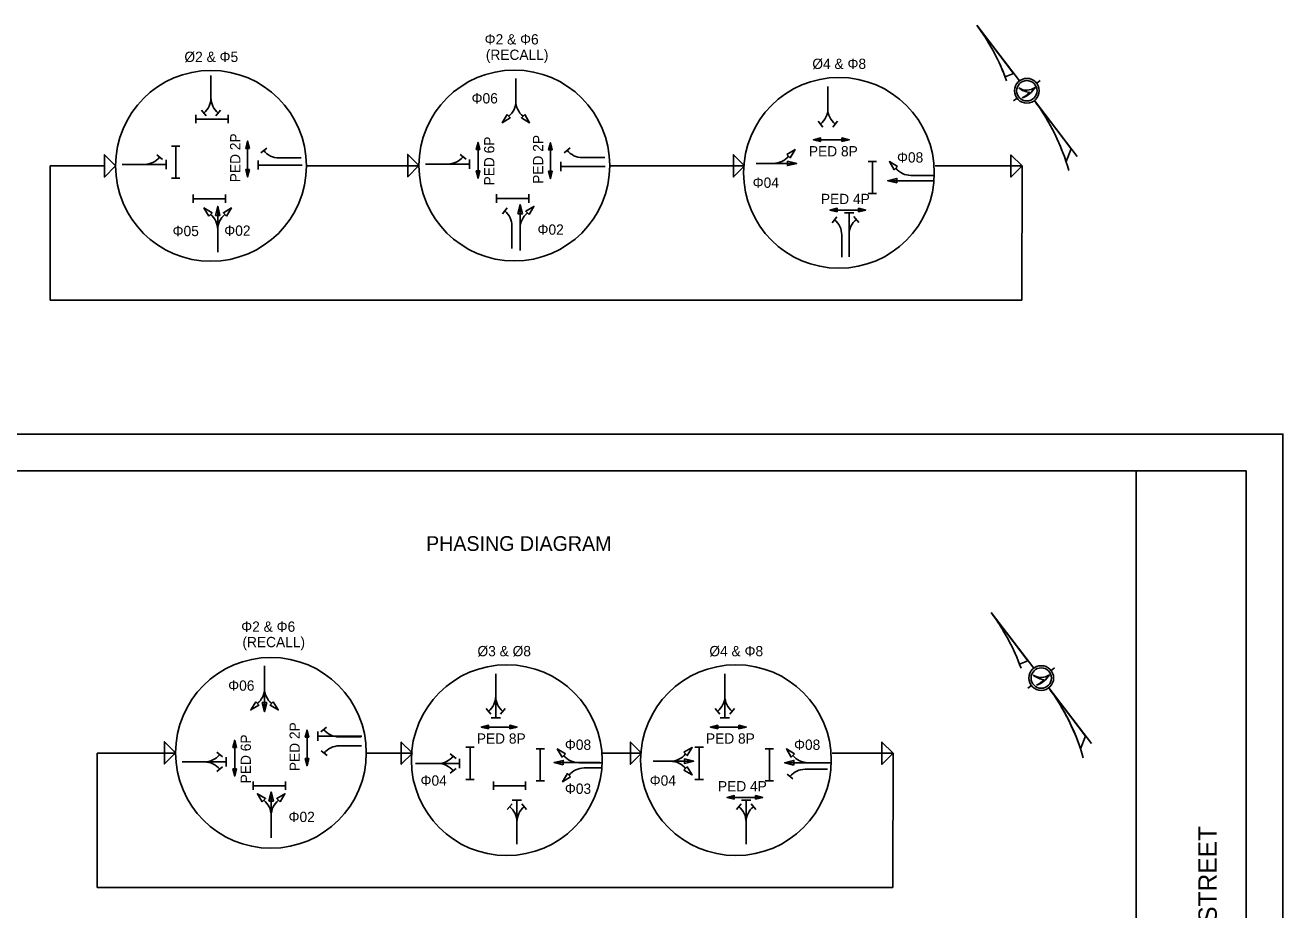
# Model space of a CAD drawing. Extents: x 0 to 680, y 0 to 551.
# Drawn here: x 337.3 to 680, y 310.4 to 551.4 of the extents above; entities that cross this region are included whole.
import ezdxf

# ---------------------------------------------------------------- set-up
doc = ezdxf.new("R2010")
doc.units = 0
for name, color, linetype in [('SG_P_Text', 7, 'Continuous'), ('SH_Border', 7, 'Continuous'), ('SH_Cut_Line', 7, 'Continuous'), ('SH_Data', 7, 'Continuous'), ('SH_Text', 7, 'Continuous')]:
    doc.layers.add(name, color=color, linetype=linetype)

msp = doc.modelspace()

# ---------------------------------------------------------------- linework, layer by layer
at = {"layer": 'SG_P_Text'}
for p, q in [((387.94, 537.7), (387.94, 531.59)), ((387.94, 537.7), (387.94, 531.59)), ((471, 536.85), (471, 530.74)), ((471.04, 536.85), (471.04, 530.74)), ((556.02, 534.7), (556.02, 528.59)), ((556.02, 534.7), (556.02, 528.59)), ((386.6, 526.66), (385.32, 528.25)), ((389.28, 526.66), (390.56, 528.25)), ((383.82, 526.97), (383.82, 524.69)), ((383.82, 525.83), (392.59, 525.83)), ((392.59, 526.97), (392.59, 524.69)), ((554.68, 523.66), (553.4, 525.25)), ((557.35, 523.66), (558.64, 525.25)), ((379.49, 518.46), (377.2, 518.46)), ((378.35, 509.68), (378.35, 518.46)), ((397.91, 510.06), (397.91, 519.82)), ((401.53, 516.58), (403.12, 517.86)), ((460.74, 509.71), (460.74, 519.47)), ((480.43, 509.63), (480.43, 519.38)), ((484.19, 516.67), (485.78, 517.95)), ((552.08, 520.19), (561.84, 520.19)), ((374.76, 514.83), (373.17, 516.11)), ((375.74, 514.76), (375.74, 512.22)), ((400.79, 512.04), (400.79, 514.57)), ((412.56, 515.24), (406.45, 515.24)), ((457.43, 514.91), (455.83, 516.19)), ((458.4, 514.84), (458.4, 512.31)), ((483.31, 511.6), (483.31, 514.14)), ((495.23, 515.33), (489.12, 515.33)), ((569.3, 514.3), (567.01, 514.3)), ((568.16, 505.52), (568.16, 514.3)), ((344.11, 476.49), (344.17, 513.07)), ((344.17, 513.07), (358.92, 513.07)), ((363.72, 513.49), (375.74, 513.49)), ((363.72, 513.49), (369.83, 513.49)), ((412.8, 513.3), (400.79, 513.3)), ((444.61, 513.08), (413.93, 513.07)), ((446.39, 513.57), (458.4, 513.57)), ((446.39, 513.57), (452.5, 513.57)), ((495.32, 512.87), (483.31, 512.87)), ((533.31, 513.08), (496.59, 513.08)), ((536.52, 513.76), (541.19, 513.76)), ((547.54, 513.76), (536.52, 513.76)), ((608.94, 513.05), (585.29, 513.08)), ((608.88, 476.49), (608.94, 513.05)), ((379.49, 509.68), (377.2, 509.68)), ((572.33, 509.04), (584.79, 509.04)), ((584.79, 510.47), (578.68, 510.47)), ((383.11, 505.24), (383.11, 502.96)), ((391.89, 504.1), (383.11, 504.1)), ((391.89, 505.24), (391.89, 502.96)), ((465.78, 505.33), (465.78, 503.04)), ((474.55, 504.19), (465.78, 504.19)), ((474.55, 505.33), (474.55, 503.04)), ((569.3, 505.52), (567.01, 505.52)), ((389.78, 502.06), (389.78, 489.6)), ((468.63, 501.6), (467.34, 500)), ((472.18, 502.47), (472.18, 490.01)), ((556.6, 501.03), (566.35, 501.03)), ((558.48, 499.19), (557.2, 497.6)), ((560.54, 500.26), (563.08, 500.26)), ((561.81, 488.25), (561.81, 500.26)), ((563.15, 499.29), (564.43, 497.69)), ((389.78, 489.6), (389.78, 495.71)), ((389.78, 489.6), (389.78, 495.71)), ((469.96, 490.56), (469.96, 496.67)), ((472.18, 490.01), (472.18, 496.12)), ((559.82, 488.16), (559.82, 494.27)), ((561.81, 488.25), (561.81, 494.36)), ((608.88, 476.49), (344.11, 476.49)), ((402.51, 376.85), (402.51, 370.74)), ((402.55, 376.85), (402.55, 370.74)), ((402.55, 364.39), (402.55, 376.85)), ((465.52, 374.7), (465.52, 368.59)), ((465.52, 374.7), (465.52, 368.59)), ((465.52, 374.7), (465.52, 362.69)), ((527.96, 374.7), (527.96, 368.59)), ((527.96, 374.7), (527.96, 368.59)), ((527.96, 374.7), (527.96, 362.69)), ((464.18, 363.66), (462.9, 365.25)), ((466.86, 363.66), (468.14, 365.25)), ((526.62, 363.66), (525.34, 365.25)), ((529.3, 363.66), (530.58, 365.25)), ((417.87, 358.87), (419.46, 360.15)), ((461.59, 360.19), (471.34, 360.19)), ((466.79, 362.69), (464.25, 362.69)), ((524.03, 360.19), (533.78, 360.19)), ((529.23, 362.69), (526.69, 362.69)), ((394.42, 346.84), (394.42, 356.59)), ((414.11, 349.63), (414.11, 359.38)), ((417.04, 356.41), (417.04, 358.95)), ((429.05, 357.68), (417.04, 357.68)), ((428.91, 357.52), (422.8, 357.53)), ((356.9, 316.49), (356.96, 353.08)), ((378.29, 353.08), (356.96, 353.08)), ((391.11, 352.04), (389.51, 353.32)), ((417.96, 353.73), (419.56, 352.45)), ((429, 355.07), (422.89, 355.07)), ((442.62, 353.08), (430.27, 353.08)), ((459.66, 354.72), (457.38, 354.72)), ((458.52, 345.94), (458.52, 354.72)), ((478.8, 354.3), (476.52, 354.3)), ((477.66, 345.52), (477.66, 354.3)), ((505.25, 353.08), (494.46, 353.08)), ((522.1, 354.72), (519.82, 354.72)), ((520.96, 345.94), (520.96, 354.72)), ((541.24, 354.3), (538.96, 354.3)), ((540.1, 345.52), (540.1, 354.3)), ((573.8, 353.05), (557.24, 353.08)), ((573.74, 316.49), (573.8, 353.05)), ((380.07, 350.7), (392.08, 350.7)), ((380.07, 350.7), (386.18, 350.7)), ((380.07, 350.7), (386.18, 350.7)), ((392.08, 351.96), (392.08, 349.43)), ((443.69, 350.26), (455.7, 350.26)), ((443.69, 350.26), (449.8, 350.26)), ((443.69, 350.26), (449.8, 350.26)), ((454.73, 351.6), (453.13, 352.88)), ((455.7, 351.53), (455.7, 349)), ((481.44, 350.5), (493.9, 350.5)), ((494.3, 350.47), (488.19, 350.48)), ((508.47, 350.88), (513.13, 350.88)), ((519.48, 350.88), (508.47, 350.88)), ((508.47, 350.88), (513.13, 350.88)), ((544.28, 350.47), (556.74, 350.47)), ((556.74, 350.47), (550.63, 350.48)), ((391.11, 349.36), (389.51, 348.08)), ((454.73, 348.92), (453.13, 347.64)), ((494.3, 349.04), (489.63, 349.04)), ((544.9, 347.36), (546.5, 346.08)), ((555.94, 348.7), (549.83, 348.7)), ((399.46, 345.33), (399.46, 343.05)), ((408.23, 344.19), (399.46, 344.19)), ((408.23, 345.33), (408.23, 343.05)), ((459.66, 345.94), (457.38, 345.94)), ((464.9, 345.33), (464.9, 343.05)), ((473.67, 344.19), (464.9, 344.19)), ((473.67, 345.33), (473.67, 343.05)), ((478.8, 345.52), (476.52, 345.52)), ((522.1, 345.94), (519.82, 345.94)), ((541.24, 345.52), (538.96, 345.52)), ((404.34, 342.47), (404.34, 330.01)), ((469.97, 339.29), (468.69, 337.69)), ((470.04, 340.26), (472.58, 340.26)), ((471.31, 328.25), (471.31, 340.26)), ((472.65, 339.29), (473.93, 337.69)), ((528.55, 341.03), (538.3, 341.03)), ((532.41, 339.29), (531.13, 337.69)), ((532.48, 340.26), (535.02, 340.26)), ((533.75, 328.25), (533.75, 340.26)), ((535.09, 339.29), (536.37, 337.69)), ((404.34, 330.01), (404.34, 336.12)), ((404.34, 330.01), (404.34, 336.12)), ((471.31, 328.25), (471.31, 334.36)), ((471.31, 328.25), (471.31, 334.36)), ((533.75, 328.25), (533.75, 334.36)), ((533.75, 328.25), (533.75, 334.36)), ((573.74, 316.49), (356.9, 316.49))]:
    msp.add_line(p, q, dxfattribs=at)
for points in [[(468.62, 527.05), (467.29, 524.83), (469.5, 526.16)], [(473.42, 527.05), (474.75, 524.83), (472.54, 526.16)], [(398.41, 517.84), (397.91, 519.82), (397.42, 517.84)], [(461.23, 517.49), (460.74, 519.47), (460.24, 517.49)], [(480.93, 517.4), (480.43, 519.38), (479.94, 517.4)], [(544.88, 516.18), (547.09, 517.51), (545.76, 515.3)], [(554.06, 519.7), (552.08, 520.19), (554.06, 520.69)], [(559.86, 519.7), (561.84, 520.19), (559.86, 520.69)], [(361.95, 513.07), (358.92, 516.11), (358.91, 510.04)], [(444.61, 513.16), (441.58, 516.19), (441.58, 510.13)], [(533.31, 513.08), (530.28, 516.11), (530.28, 510.05)], [(545.04, 514.39), (547.54, 513.76), (545.04, 513.14)], [(574.99, 512.9), (572.78, 514.22), (574.11, 512.01)], [(608.94, 513.05), (605.91, 516.08), (605.91, 510.02)], [(398.41, 512.04), (397.91, 510.06), (397.42, 512.04)], [(461.23, 511.69), (460.74, 509.71), (460.24, 511.69)], [(480.93, 511.61), (480.43, 509.63), (479.94, 511.61)], [(574.83, 508.41), (572.33, 509.04), (574.83, 509.66)], [(387.36, 499.4), (386.03, 501.62), (388.24, 500.29)], [(389.15, 499.56), (389.78, 502.06), (390.4, 499.56)], [(392.2, 499.4), (393.53, 501.61), (391.32, 500.29)], [(471.55, 499.97), (472.18, 502.47), (472.8, 499.97)], [(474.6, 499.81), (475.92, 502.02), (473.72, 500.69)], [(558.58, 500.54), (556.6, 501.03), (558.58, 501.53)], [(564.38, 500.54), (566.35, 501.03), (564.38, 501.53)], [(400.13, 367.05), (398.8, 364.84), (401.01, 366.17)], [(403.17, 366.89), (402.55, 364.39), (401.92, 366.89)], [(404.93, 367.05), (406.26, 364.84), (404.05, 366.17)], [(463.57, 359.7), (461.59, 360.19), (463.57, 360.69)], [(469.36, 359.7), (471.34, 360.19), (469.36, 360.69)], [(526.01, 359.7), (524.03, 360.19), (526.01, 360.69)], [(531.8, 359.7), (533.78, 360.19), (531.8, 360.69)], [(394.91, 354.61), (394.42, 356.59), (393.92, 354.61)], [(414.61, 357.41), (414.11, 359.38), (413.62, 357.41)], [(378.29, 353.16), (375.26, 356.19), (375.26, 350.13)], [(442.81, 353.08), (439.78, 356.11), (439.78, 350.05)], [(484.5, 352.9), (482.28, 354.22), (483.61, 352.01)], [(505.25, 353.08), (502.22, 356.11), (502.22, 350.05)], [(516.82, 353.31), (519.04, 354.63), (517.71, 352.42)], [(546.94, 352.9), (544.73, 354.22), (546.05, 352.01)], [(573.8, 353.05), (570.77, 356.09), (570.77, 350.02)], [(414.61, 351.61), (414.11, 349.63), (413.62, 351.61)], [(483.94, 349.87), (481.44, 350.5), (483.94, 351.12)], [(516.98, 351.51), (519.48, 350.88), (516.98, 350.26)], [(546.78, 349.85), (544.28, 350.47), (546.78, 351.1)], [(394.91, 348.82), (394.42, 346.84), (393.92, 348.82)], [(485.94, 346.62), (483.73, 345.29), (485.06, 347.5)], [(516.82, 348.46), (519.04, 347.14), (517.71, 349.35)], [(401.92, 339.81), (400.6, 342.02), (402.8, 340.69)], [(403.72, 339.97), (404.34, 342.47), (404.97, 339.97)], [(406.77, 339.81), (408.09, 342.02), (405.88, 340.69)], [(530.52, 340.54), (528.55, 341.03), (530.52, 341.53)], [(536.32, 340.54), (538.3, 341.03), (536.32, 341.53)]]:
    msp.add_lwpolyline(points, close=True, dxfattribs=at)
for centre in [(387.94, 513.07), (470.6, 513.16), (559.04, 511.17), (404.28, 353.16), (468.54, 351.17), (530.98, 351.17)]:
    msp.add_circle(centre, 25.99, dxfattribs=at)
for centre, start, end in [((382.64, 531.59), 308.7993, 0), ((393.24, 531.59), 180, 231.2007), ((465.74, 530.74), 308.7993, 0), ((476.3, 530.74), 180, 231.2007), ((550.72, 528.59), 308.7993, 0), ((561.32, 528.59), 180, 231.2007), ((369.83, 518.79), 270, 321.2007), ((406.46, 520.54), 218.7864, 269.9871), ((452.5, 518.87), 270, 321.2007), ((489.12, 520.63), 218.7864, 269.9871), ((541.19, 519.06), 270, 321.2007), ((578.68, 515.77), 218.7864, 269.9871), ((464.66, 496.67), 360, 51.2007), ((384.48, 495.71), 360, 51.2007), ((395.08, 495.71), 128.7864, 179.9871), ((477.48, 496.12), 128.7864, 179.9871), ((554.52, 494.27), 360, 51.2007), ((567.11, 494.36), 128.7993, 180), ((397.25, 370.74), 308.7993, 0), ((407.81, 370.74), 180, 231.2007), ((460.22, 368.59), 308.7993, 0), ((470.82, 368.59), 180, 231.2007), ((522.66, 368.59), 308.7993, 0), ((533.26, 368.59), 180, 231.2007), ((422.8, 362.83), 218.7864, 269.9871), ((422.89, 349.77), 90.0129, 141.2136), ((386.18, 356), 270, 321.2007), ((386.18, 345.4), 38.7993, 90), ((449.8, 355.56), 270, 321.2007), ((449.8, 344.96), 38.7993, 90), ((488.19, 355.78), 218.7864, 269.9871), ((513.13, 356.18), 270, 321.2007), ((513.13, 345.58), 38.7993, 90), ((550.63, 355.78), 218.7864, 269.9871), ((489.63, 343.74), 90, 141.2007), ((549.83, 343.4), 90.0129, 141.2136), ((399.04, 336.12), 0.0129, 51.2136), ((409.65, 336.12), 128.7864, 179.9871), ((466.01, 334.36), 360, 51.2007), ((476.61, 334.36), 128.7993, 180), ((528.45, 334.36), 360, 51.2007), ((539.05, 334.36), 128.7993, 180)]:
    msp.add_arc(centre, 5.3, start, end, dxfattribs=at)
at = {"layer": 'SH_Border'}
msp.add_line((640, 10), (640, 430), dxfattribs=at)
msp.add_lwpolyline([(30, 430), (670, 430), (670, 10), (30, 10)], close=True, dxfattribs=at)
at = {"layer": 'SH_Cut_Line'}
msp.add_lwpolyline([(0, 0), (680, 0), (680, 440), (0, 440)], close=True, dxfattribs=at)
at = {"layer": 'SH_Data'}
for p, q in [((608.2, 536.22), (596.58, 551.41)), ((604.34, 537.33), (606.64, 538.26)), ((612.93, 535.59), (613.89, 536.32)), ((606.62, 530.76), (607.57, 531.49)), ((623.92, 515.67), (612.3, 530.86)), ((622.33, 517.75), (620.95, 514.26)), ((612.12, 376.22), (600.5, 391.41)), ((608.26, 377.33), (610.56, 378.27)), ((616.86, 375.59), (617.81, 376.32)), ((610.54, 370.76), (611.49, 371.49)), ((627.85, 355.67), (616.23, 370.86)), ((626.25, 357.75), (624.87, 354.27))]:
    msp.add_line(p, q, dxfattribs=at)
for points in [[(604.33, 537.32), (604.34, 537.33), (606.64, 538.26), (596.58, 551.41)], [(620.95, 514.26), (622.33, 517.75), (612.3, 530.86)], [(608.25, 377.33), (608.26, 377.33), (610.56, 378.27), (600.5, 391.41)], [(624.87, 354.27), (626.25, 357.75), (616.23, 370.86)]]:
    msp.add_lwpolyline(points, dxfattribs=at)
for centre, radius in [((610.25, 533.54), 3.37), ((610.25, 533.54), 2.78), ((614.17, 373.54), 3.37), ((614.17, 373.54), 2.78)]:
    msp.add_circle(centre, radius, dxfattribs=at)
for centre, radius, start, end in [((549.11, 516.14), 59.14, 19.8318, 36.6112), ((549.11, 516.14), 59.14, 20.9919, 36.6112), ((610.19, 537.51), 3.82, 236.574, 306.7874), ((611.52, 538.45), 5.38, 230.2721, 264.7306), ((606.67, 537.95), 6.79, 289.9039, 328.9025), ((604.93, 539.13), 8.57, 298.1442, 315.2899), ((564.83, 495.59), 59.14, 15.9219, 36.6112), ((564.83, 495.59), 59.14, 18.4101, 36.6112), ((553.03, 356.14), 59.14, 19.8318, 36.6112), ((553.03, 356.14), 59.14, 20.9919, 36.6112), ((614.11, 377.51), 3.82, 236.574, 306.7874), ((615.44, 378.45), 5.38, 230.2721, 264.7306), ((610.59, 377.95), 6.79, 289.9039, 328.9025), ((608.86, 379.13), 8.57, 298.1442, 315.2899), ((568.75, 335.59), 59.14, 15.9219, 36.6112), ((568.75, 335.59), 59.14, 18.4101, 36.6112)]:
    msp.add_arc(centre, radius, start, end, dxfattribs=at)

# ---------------------------------------------------------------- texts
at = {"layer": 'SG_P_Text'}
for s, p in [('Φ2 & Φ6', (462.51, 546.15)), ('(RECALL)', (462.83, 541.95)), (' Ø2 & Φ5', (379.67, 541.38)), (' Ø4 & Φ8', (550.76, 539.48)), ('Φ06', (458.95, 530.08)), ('Φ08', (574.87, 513.98)), ('Φ04', (535.54, 507.1)), ('Φ02', (476.92, 494.32)), ('Φ05', (377.49, 493.93)), ('Φ02', (391.56, 494.03)), ('Φ2 & Φ6', (396.18, 386.15)), ('(RECALL)', (396.51, 381.95)), (' Ø3 & Ø8 ', (459.52, 379.48)), (' Ø4 & Φ8', (522.71, 379.48)), ('Φ06', (392.63, 370.09)), ('Φ08', (484.37, 353.98)), ('Φ08', (546.81, 353.98)), ('Φ04', (445.04, 344.22)), ('Φ04', (507.48, 344.22)), ('Φ03', (484.37, 342)), ('Φ02', (409.08, 334.32))]:
    msp.add_text(s, height=2.8, dxfattribs=at).set_placement(p)
for s, rotation, p in [('PED 2P', 90, (395.95, 508.6)), ('PED 2P', 90, (478.47, 508.17)), ('PED 6P', 90, (465.15, 507.74)), ('PED 8P', 360, (550.86, 515.66)), ('PED 4P', 360, (554.13, 502.66)), ('PED 2P', 90, (412.15, 348.17)), ('PED 6P', 90, (398.83, 344.86)), ('PED 8P', 360, (460.37, 355.67)), ('PED 8P', 360, (522.81, 355.67)), ('PED 4P', 360, (526.08, 342.67))]:
    msp.add_text(s, height=2.8, rotation=rotation, dxfattribs=at).set_placement(p)
at = {"layer": 'SH_Data'}
msp.add_text('SOUTH MAIN STREET & WEST 6TH STREET', height=5, rotation=90, dxfattribs=at).set_placement((662, 192.82))
at = {"layer": 'SH_Text'}
msp.add_text('PHASING DIAGRAM', height=4, dxfattribs=at).set_placement((446.55, 408.19))

doc.saveas('drawing.dxf')
